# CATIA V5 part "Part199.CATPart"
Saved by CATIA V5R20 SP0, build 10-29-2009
Part number: FA 168700-2 comprimido
Revision: ANY
Definition: UNKNOWN
Nomenclature: FA 168700-2 comprimido
Source: Unknown
Bounding box of the stored display mesh (mm): x -2.8 to 2.8, y 0 to 4.04, z -2.8 to 2.8
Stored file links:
  C:\Users\Utente\Desktop\IO LAVORO\3D X SITO CF\CUMSA\3D files FA\FA 168712-20\Part199.CATPart

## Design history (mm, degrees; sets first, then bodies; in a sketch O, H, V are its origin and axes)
Body1 "Cortar-Extruir1" (main body)
  Solid1: solid without history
